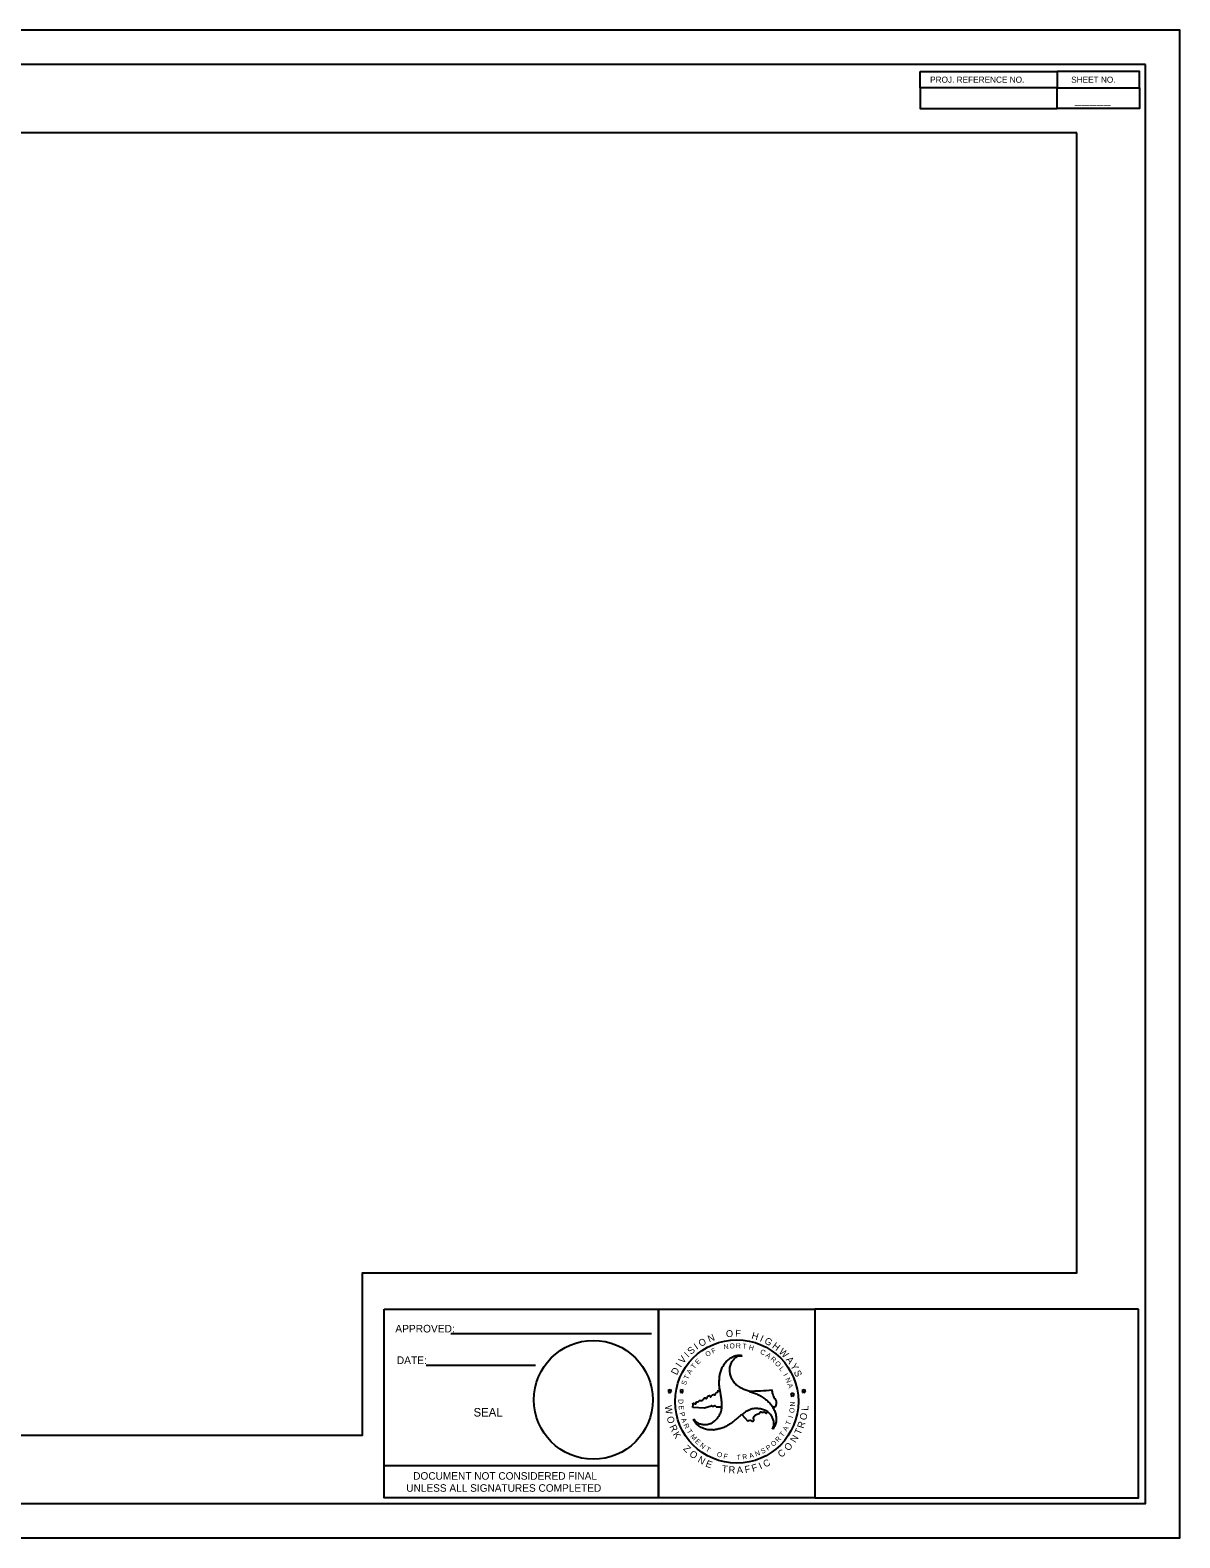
# Model space of a CAD drawing. Extents: x -38542 to 45858, y -25814 to 29186.
# Drawn here: x 3934 to 45858, y -25814 to 29186 of the extents above; entities that cross this region are included whole.
import ezdxf

# ---------------------------------------------------------------- set-up
doc = ezdxf.new("R2010")
doc.units = 0
for name, color, linetype in [('DEV TYPE 3 BARRICADE CELL', 7, 'Continuous'), ('DEV TYPE 3 BARRICADE WITH R11-2 M4-10R CELL', 7, 'Continuous'), ('Sheet Plot Border Outside CELL', 7, 'Continuous'), ('WZ DETAHD CELL', 7, 'Continuous'), ('WZ RC1000 CELL', 7, 'Continuous'), ('WZ RCANL CELL', 7, 'Continuous')]:
    doc.layers.add(name, color=color, linetype=linetype)

msp = doc.modelspace()

# ---------------------------------------------------------------- linework, layer by layer
at = {"layer": 'DEV TYPE 3 BARRICADE CELL'}
msp.add_lwpolyline([(42108, 25436), (-27892, 25436), (-27892, -22064), (16051, -22064), (16051, -16151), (42108, -16151)], close=True, dxfattribs=at)
at = {"layer": 'DEV TYPE 3 BARRICADE WITH R11-2 M4-10R CELL'}
msp.add_circle((29701, -20840), 2249, dxfattribs=at)
at = {"layer": 'Sheet Plot Border Outside CELL'}
msp.add_lwpolyline([(-38542, -25814), (45858, -25814), (45858, 29186), (-38542, 29186)], close=True, dxfattribs=at)
at = {"layer": 'WZ DETAHD CELL'}
for p, q in [((16849, -24351), (16849, -23176)), ((16849, -23176), (26851, -23176)), ((26851, -23176), (26851, -24351)), ((26851, -24351), (16849, -24351))]:
    msp.add_line(p, q, dxfattribs=at)
at = {"layer": 'WZ RC1000 CELL'}
for p, q in [((41390, 27079), (44390, 27079)), ((19276, -18360), (26593, -18360)), ((26851, -18651), (26851, -24351)), ((18370, -19514), (22360, -19514))]:
    msp.add_line(p, q, dxfattribs=at)
for points in [[(44608, 27936), (-30392, 27936), (-30392, -24564), (44608, -24564)], [(36390, 27679), (41390, 27679), (41390, 27079), (36390, 27079)], [(41390, 27079), (44390, 27079), (44390, 27679), (41390, 27679)], [(41390, 27079), (36390, 27079), (36390, 26329), (41390, 26329)], [(41390, 27079), (44390, 27079), (44390, 26329), (41390, 26329)], [(16849, -17476), (26851, -17476), (26851, -24351), (16849, -24351)], [(26851, -17476), (32551, -17476), (32551, -24351), (26851, -24351)], [(44351, -17476), (32551, -17476), (32551, -24351), (44351, -24351)]]:
    msp.add_lwpolyline(points, close=True, dxfattribs=at)
msp.add_circle((24471, -20780), 2167, dxfattribs=at)
at = {"layer": 'WZ RCANL CELL'}
for p, q in [((27187, -20443), (27231, -20475)), ((27241, -20443), (27187, -20443)), ((27231, -20475), (27215, -20527)), ((27215, -20527), (27257, -20495)), ((27257, -20392), (27241, -20443)), ((27275, -20443), (27257, -20392)), ((27257, -20495), (27302, -20527)), ((27257, -20495), (27301, -20527)), ((27329, -20443), (27275, -20443)), ((27285, -20475), (27330, -20443)), ((27285, -20475), (27329, -20443)), ((27302, -20527), (27285, -20475)), ((27301, -20527), (27285, -20475)), ((27675, -20443), (27621, -20443)), ((27621, -20443), (27665, -20475)), ((27665, -20475), (27649, -20528)), ((27649, -20528), (27691, -20495)), ((27691, -20393), (27675, -20443)), ((27709, -20443), (27691, -20393)), ((27691, -20495), (27735, -20528)), ((27763, -20443), (27709, -20443)), ((27719, -20475), (27763, -20443)), ((27735, -20528), (27719, -20475)), ((31714, -20568), (31659, -20568)), ((31659, -20568), (31703, -20600)), ((31703, -20600), (31687, -20652)), ((31687, -20652), (31730, -20620)), ((31730, -20518), (31714, -20568)), ((31748, -20568), (31730, -20518)), ((31730, -20620), (31774, -20652)), ((31802, -20568), (31748, -20568)), ((31758, -20600), (31802, -20568)), ((31774, -20652), (31758, -20600)), ((32127, -20436), (32073, -20436)), ((32073, -20436), (32117, -20468)), ((32117, -20468), (32101, -20520)), ((32101, -20520), (32143, -20488)), ((32143, -20385), (32127, -20436)), ((32161, -20436), (32143, -20385)), ((32143, -20488), (32188, -20520)), ((32216, -20436), (32161, -20436)), ((32172, -20468), (32216, -20436)), ((32188, -20520), (32172, -20468)), ((28103, -21065), (28107, -20932)), ((28523, -21080), (28103, -21065)), ((28763, -21010), (28523, -21080)), ((28948, -21038), (29159, -21040)), ((29886, -21319), (30101, -21552))]:
    msp.add_line(p, q, dxfattribs=at)
for start, end in [(265.6785, 265.9762), (271.2035, 275.3236)]:
    msp.add_arc((29905, -8806), 11660, start, end, dxfattribs=at)
for points in [[(28124, -21470), (28211, -21571), (28320, -21641), (28445, -21673), (28586, -21681), (28729, -21648), (28825, -21599), (28865, -21567), (28935, -21512), (28984, -21458), (29067, -21340), (29132, -21201), (29159, -21041), (29160, -21027), (29159, -20877), (29139, -20725), (29117, -20579), (29090, -20428), (29066, -20277), (29063, -20131), (29073, -19963), (29097, -19819), (29144, -19672), (29169, -19602), (29204, -19546), (29292, -19413), (29406, -19306), (29481, -19249), (29552, -19211), (29564, -19205), (29706, -19159), (29846, -19154), (29893, -19166)], [(29897, -19162), (29893, -19166), (29764, -19190), (29647, -19250), (29557, -19342), (29481, -19458), (29438, -19601), (29431, -19707), (29441, -19758), (29453, -19846), (29473, -19916), (29536, -20046), (29623, -20172), (29749, -20276), (29760, -20284), (29889, -20358), (30033, -20417), (30169, -20470), (30313, -20523), (30455, -20579), (30584, -20649), (30725, -20740), (30836, -20833), (30941, -20947), (30990, -21005), (31020, -21064), (31093, -21205), (31128, -21358), (31140, -21452), (31137, -21532), (31137, -21546), (31104, -21692), (31038, -21815), (31006, -21849)], [(28107, -20932), (28103, -20919), (28126, -20905), (28188, -20931), (28219, -20904), (28218, -20877), (28243, -20850), (28285, -20859), (28324, -20810), (28359, -20801), (28434, -20801), (28523, -20712), (28560, -20706), (28569, -20730), (28592, -20734), (28632, -20661), (28642, -20651), (28709, -20623), (28728, -20637), (28733, -20669), (28743, -20675), (28766, -20659), (28797, -20620), (28853, -20590), (28918, -20599), (28930, -20545), (29006, -20494), (29022, -20463), (29026, -20432)], [(31002, -21026), (31125, -21011), (31144, -20914), (31145, -20832), (31094, -20737), (31018, -20563), (30987, -20415)], [(31006, -21849), (31049, -21725), (31055, -21595), (31020, -21470), (30957, -21346), (30857, -21238), (30768, -21179), (30718, -21162), (30638, -21127), (30564, -21111), (30422, -21099), (30267, -21112), (30116, -21170), (30104, -21175), (29975, -21252), (29853, -21344), (29736, -21435), (29619, -21535), (29500, -21631), (29375, -21707), (29224, -21783), (29089, -21833), (28939, -21866), (28863, -21880), (28798, -21877), (28641, -21869), (28489, -21823), (28403, -21787), (28335, -21743), (28323, -21736), (28212, -21635), (28139, -21517), (28124, -21470)], [(28948, -21038), (28931, -21005), (28897, -20996), (28851, -21020), (28817, -21018), (28779, -20990), (28763, -21010)], [(30101, -21552), (30186, -21527), (30256, -21554), (30290, -21559), (30319, -21538), (30310, -21432), (30334, -21383), (30449, -21298), (30519, -21282), (30572, -21217), (30593, -21219), (30625, -21237), (30697, -21223), (30755, -21270), (30789, -21267), (30816, -21214)]]:
    msp.add_spline(points, degree=3, dxfattribs=at)

# ---------------------------------------------------------------- texts
at = {"layer": 'DEV TYPE 3 BARRICADE WITH R11-2 M4-10R CELL'}
for s, height, rotation, p in [('T', 181, 353.7884, (29901, -18905)), ('W', 252, 278.15, (27075, -21000)), ('O', 252, 287.1147, (27136, -21421)), ('O', 252, 78.9896, (32236, -21537)), ('L', 252, 87.429, (32310, -21179)), ('R', 252, 295.5541, (27234, -21759)), ('K', 252, 301.7918, (27357, -22036)), ('T', 252, 66.881, (32023, -22078)), ('R', 252, 72.7519, (32135, -21843)), ('Z', 252, 316.1688, (27729, -22582)), ('O', 252, 50.4526, (31595, -22664)), ('N', 252, 58.892, (31842, -22365)), ('O', 252, 322.5233, (27947, -22799)), ('N', 252, 330.9626, (28254, -23036)), ('E', 252, 338.9517, (28541, -23203)), ('I', 252, 23.7503, (30569, -23323)), ('C', 252, 28.0033, (30741, -23257)), ('C', 252, 43.0807, (31333, -22903)), ('T', 252, 352.6948, (29143, -23412)), ('R', 252, 358.5656, (29400, -23455)), ('A', 252, 4.8034, (29710, -23471)), ('F', 252, 11.7751, (30015, -23453)), ('F', 252, 17.7627, (30286, -23406))]:
    msp.add_text(s, height=height, rotation=rotation, dxfattribs=at).set_placement(p)
at = {"layer": 'WZ DETAHD CELL'}
for s, p in [('DOCUMENT NOT CONSIDERED FINAL', (17902, -23693)), ('UNLESS ALL SIGNATURES COMPLETED', (17649, -24133))]:
    msp.add_text(s, height=275, dxfattribs=at).set_placement(p)
at = {"layer": 'WZ RC1000 CELL'}
for s, height, p in [('PROJ. REFERENCE NO.', 224.43, (36753, 27267)), ('SHEET NO.', 224.4, (41896, 27267))]:
    msp.add_text(s, height=height, rotation=0.0006, dxfattribs=at).set_placement(p)
for s, height, p in [('   _____  ', 350, (41640, 26529)), ('APPROVED:  ', 277.83, (17250, -18322)), ('DATE:  ', 277.8, (17304, -19473)), ('SEAL', 310.2, (20102, -21388))]:
    msp.add_text(s, height=height, dxfattribs=at).set_placement(p)
at = {"layer": 'WZ RCANL CELL'}
for s, height, rotation, p in [('O', 252, 30.0935, (28392, -18857)), ('N', 252, 21.5861, (28699, -18688)), ('O', 252, 5.7649, (29319, -18503)), ('F', 252, 357.2575, (29641, -18475)), ('H', 252, 343.454, (30220, -18540)), ('I', 252, 335.804, (30522, -18634)), ('G', 252, 331.5167, (30684, -18704)), ('H', 252, 323.4632, (30969, -18864)), ('V', 252, 51.5806, (27748, -19477)), ('I', 252, 44.8722, (27928, -19253)), ('S', 252, 40.5848, (28032, -19143)), ('I', 252, 34.3808, (28244, -18961)), ('O', 181, 29.335, (28614, -19219)), ('F', 181, 24.2569, (28825, -19100)), ('N', 181, 9.0227, (29237, -18944)), ('O', 181, 3.9446, (29443, -18908)), ('R', 181, 358.8665, (29666, -18893)), ('H', 181, 343.6322, (30122, -18936)), ('C', 181, 333.4761, (30532, -19081)), ('A', 181, 323.3199, (30738, -19187)), ('R', 181, 318.2418, (30912, -19314)), ('W', 252, 315.8133, (31215, -19050)), ('A', 252, 306.7762, (31477, -19316)), ('D', 252, 63.459, (27515, -19895)), ('I', 252, 55.8679, (27660, -19615)), ('A', 181, 59.8035, (28014, -19869)), ('T', 181, 49.6473, (28144, -19667)), ('E', 181, 44.5692, (28286, -19503)), ('O', 181, 313.1637, (31073, -19459)), ('L', 181, 308.0856, (31236, -19645)), ('Y', 252, 299.7484, (31643, -19538)), ('S', 252, 293.2249, (31773, -19763)), ('S', 181, 69.9597, (27839, -20265)), ('T', 181, 64.8816, (27919, -20056)), ('I', 181, 297.9295, (31388, -19870)), ('N', 181, 292.8514, (31464, -20014)), ('A', 181, 287.7733, (31544, -20216)), ('D', 181, 270.272, (27573, -20753)), ('N', 181, 87.733, (31823, -21026)), ('E', 181, 275.3501, (27579, -20996)), ('P', 181, 285.5063, (27608, -21255)), ('I', 181, 72.7707, (31737, -21456)), ('O', 181, 82.9269, (31791, -21271)), ('A', 181, 290.5843, (27668, -21478)), ('R', 181, 295.6624, (27751, -21694)), ('T', 181, 300.7405, (27866, -21917)), ('T', 181, 52.4584, (31378, -22149)), ('A', 181, 62.6145, (31524, -21945)), ('T', 181, 67.6926, (31637, -21726)), ('M', 181, 310.8967, (27995, -22121)), ('E', 181, 315.9748, (28163, -22312)), ('N', 181, 321.0529, (28333, -22471)), ('T', 181, 331.209, (28547, -22634)), ('S', 181, 27.068, (30627, -22756)), ('P', 181, 32.146, (30832, -22642)), ('O', 181, 42.3022, (31036, -22501)), ('R', 181, 47.3803, (31213, -22339)), ('O', 181, 341.3652, (28954, -22834)), ('F', 181, 346.4433, (29201, -22908)), ('T', 181, 1.6775, (29691, -22969)), ('R', 181, 6.7556, (29912, -22957)), ('A', 181, 16.9118, (30176, -22919)), ('N', 181, 21.9899, (30406, -22850))]:
    msp.add_text(s, height=height, rotation=rotation, dxfattribs=at).set_placement(p)

doc.saveas('drawing.dxf')
